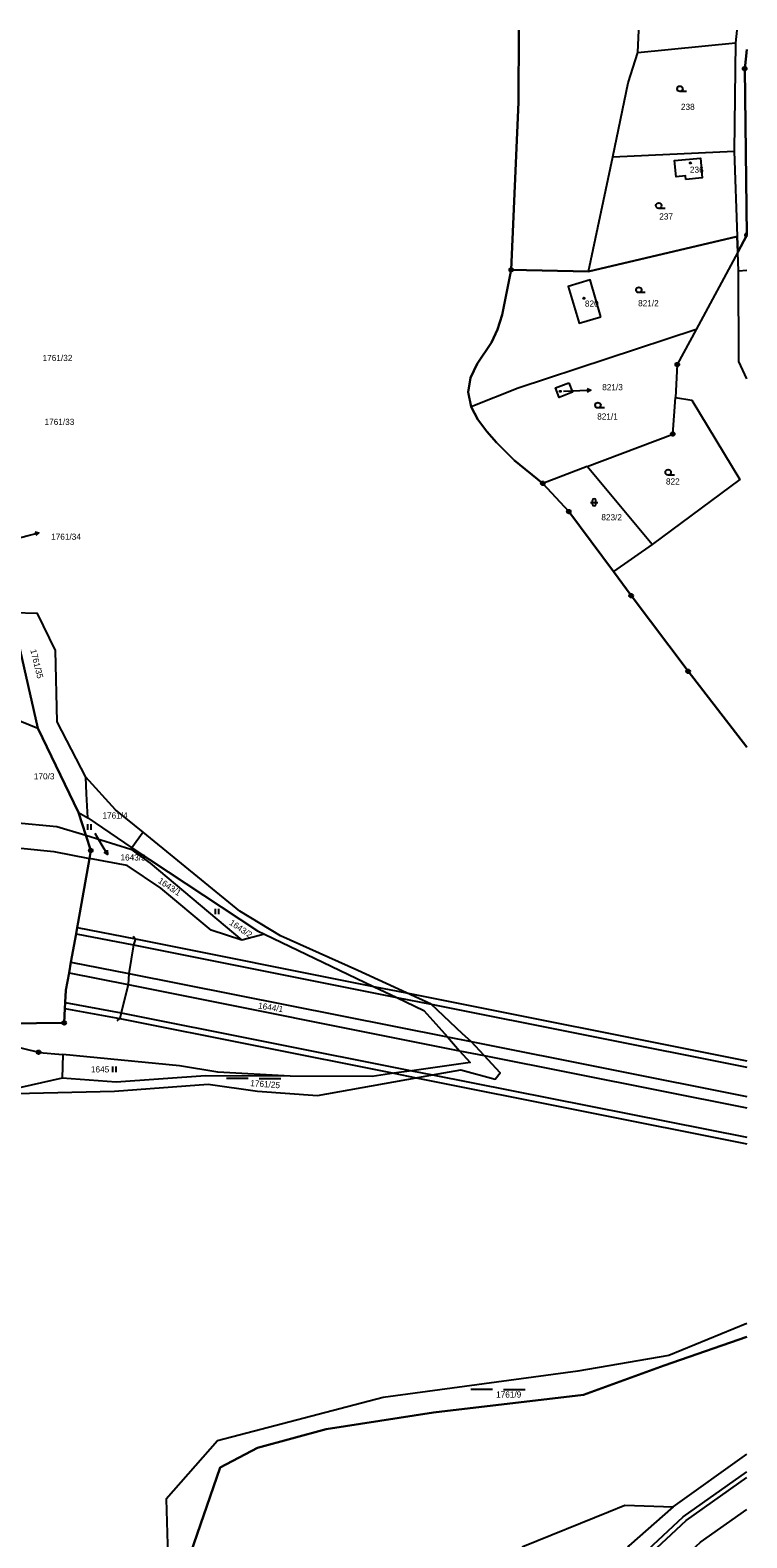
# Model space of a CAD drawing. Extents: x -737240 to -735272, y -1119606 to -1117878.
# Drawn here: x -735469.9 to -735272.2, y -1118294.6 to -1117878.3 of the extents above; entities that cross this region are included whole.
import ezdxf

# ---------------------------------------------------------------- set-up
doc = ezdxf.new("R2010")
doc.units = 0
for name, color, linetype in [('Level 1', 7, 'Continuous'), ('Level 13', 7, 'Continuous'), ('Level 16', 7, 'Continuous'), ('Level 18', 7, 'Continuous'), ('Level 19', 7, 'Continuous'), ('Level 25', 7, 'Continuous'), ('Level 4', 7, 'Continuous')]:
    doc.layers.add(name, color=color, linetype=linetype)

msp = doc.modelspace()

# ---------------------------------------------------------------- linework, layer by layer
at = {"layer": 'Level 1'}
for p, q in [((-735302.32, -1117884.48), (-735302.039, -1117878.325)), ((-735302.32, -1117884.48), (-735275.36, -1117881.8)), ((-735275.36, -1117881.8), (-735275.67, -1117911.76)), ((-735315.94, -1117944.99), (-735309.17, -1117913.32)), ((-735309.17, -1117913.32), (-735275.67, -1117911.76)), ((-735275.67, -1117911.76), (-735274.87, -1117935.26)), ((-735274.87, -1117935.26), (-735315.94, -1117944.99)), ((-735274.73, -1117939.62), (-735286.2, -1117960.98)), ((-735274.52, -1117944.82), (-735274.73, -1117939.62)), ((-735272.215, -1117944.634), (-735274.52, -1117944.82)), ((-735316.27, -1117998.81), (-735328.51, -1118003.44)), ((-735298.36, -1118020.36), (-735316.27, -1117998.81)), ((-735298.36, -1118020.36), (-735309.03, -1118027.82)), ((-735474.21, -1118042.61), (-735467.78, -1118071.06)), ((-735480.05, -1118066.06), (-735467.78, -1118071.06)), ((-735456.55, -1118094.29), (-735454.06, -1118095.76)), ((-735454.54, -1118100.61), (-735456.55, -1118094.29)), ((-735454.06, -1118095.76), (-735441.86, -1118104.02)), ((-735454.54, -1118100.61), (-735442.15, -1118104.41)), ((-735438.72, -1118099.76), (-735441.86, -1118104.02)), ((-735442.15, -1118104.41), (-735441.86, -1118104.02)), ((-735458.67, -1118135.62), (-735457.26, -1118127.77)), ((-735457.26, -1118127.77), (-735456.96, -1118126.05)), ((-735405.25, -1118127.94), (-735411.57, -1118129.59)), ((-735405.25, -1118127.94), (-735375.21, -1118142.31)), ((-735459.2, -1118138.57), (-735458.67, -1118135.62)), ((-735375.21, -1118142.31), (-735368.78, -1118145.38)), ((-735359.33, -1118147.26), (-735366.15, -1118144.12)), ((-735460.32, -1118148.43), (-735460.23, -1118146.77)), ((-735354.84, -1118156.25), (-735351.45, -1118160.06)), ((-735344.65, -1118161.42), (-735348.27, -1118157.56)), ((-735460.92, -1118161.14), (-735461.14, -1118167.68)), ((-735364.63, -1118165.59), (-735369.57, -1118166.3)), ((-735363.41, -1118167.53), (-735358.93, -1118166.72))]:
    msp.add_line(p, q, dxfattribs=at)
for points in [[(-735335.141, -1117878.325), (-735335.25, -1117898.16), (-735337.21, -1117944.47), (-735339.7, -1117956.88), (-735340.99, -1117960.95), (-735342.67, -1117964.53), (-735346.65, -1117970.41), (-735348.44, -1117974.31), (-735349.08, -1117978.3), (-735348.29, -1117982.28), (-735346.42, -1117985.78), (-735343.95, -1117989.17), (-735341.25, -1117992.15), (-735336.29, -1117997.14), (-735328.51, -1118003.44), (-735321.34, -1118011.23), (-735309.03, -1118027.82), (-735304.12, -1118034.44), (-735288.4, -1118055.33), (-735272.215, -1118076.285)], [(-735315.94, -1117944.99), (-735337.21, -1117944.47), (-735335.25, -1117898.16), (-735335.141, -1117878.325)], [(-735274.971, -1117878.325), (-735275.36, -1117881.8)], [(-735309.17, -1117913.32), (-735304.94, -1117892.88), (-735302.32, -1117884.48)], [(-735272.215, -1117883.646), (-735272.81, -1117888.96), (-735272.23, -1117934.9), (-735274.73, -1117939.62), (-735274.87, -1117935.26)], [(-735274.73, -1117939.62), (-735272.23, -1117934.9), (-735272.81, -1117888.96), (-735272.215, -1117883.646)], [(-735289.03, -1117919.53), (-735289.16, -1117918.58), (-735291.7, -1117918.79), (-735292.2, -1117914.33), (-735285.02, -1117913.65), (-735284.56, -1117919.07), (-735289.03, -1117919.53)], [(-735348.29, -1117982.28), (-735349.08, -1117978.3), (-735348.44, -1117974.31), (-735346.65, -1117970.41), (-735342.67, -1117964.53), (-735340.99, -1117960.95), (-735339.7, -1117956.88), (-735337.21, -1117944.47), (-735315.94, -1117944.99), (-735274.87, -1117935.26), (-735274.73, -1117939.62)], [(-735272.215, -1117974.589), (-735274.38, -1117969.78), (-735274.52, -1117944.82)], [(-735312.45, -1117957.43), (-735315.45, -1117947.25), (-735321.49, -1117949.1), (-735318.45, -1117959.2), (-735312.45, -1117957.43)], [(-735286.2, -1117960.98), (-735335.32, -1117977.17), (-735348.29, -1117982.28)], [(-735286.2, -1117960.98), (-735291.4, -1117970.66), (-735291.93, -1117979.78)], [(-735321.31, -1117975.66), (-735320.3, -1117978.23), (-735323.95, -1117979.72), (-735324.98, -1117977.11), (-735321.31, -1117975.66)], [(-735316.27, -1117998.81), (-735292.65, -1117989.82), (-735291.93, -1117979.78)], [(-735291.93, -1117979.78), (-735287.35, -1117980.48), (-735274.19, -1118002.37), (-735298.36, -1118020.36)], [(-735328.51, -1118003.44), (-735336.29, -1117997.14), (-735341.25, -1117992.15), (-735343.95, -1117989.17), (-735346.42, -1117985.78), (-735348.29, -1117982.28)], [(-735309.03, -1118027.82), (-735321.34, -1118011.23), (-735328.51, -1118003.44)], [(-735272.215, -1118076.285), (-735288.4, -1118055.33), (-735304.12, -1118034.44), (-735309.03, -1118027.82)], [(-735454.6, -1118084.55), (-735462.52, -1118069.26), (-735462.98, -1118049.57), (-735467.95, -1118039.37), (-735474.64, -1118039.23)], [(-735456.55, -1118094.29), (-735467.78, -1118071.06), (-735474.21, -1118042.61), (-735474.64, -1118039.23)], [(-735467.78, -1118071.06), (-735456.55, -1118094.29), (-735454.54, -1118100.61)], [(-735438.72, -1118099.76), (-735446.4, -1118093.58), (-735454.6, -1118084.55)], [(-735454.06, -1118095.76), (-735454.38, -1118089.18), (-735454.6, -1118084.55)], [(-735579.33, -1118095.15), (-735568.89, -1118093.26), (-735558.52, -1118091.47), (-735530.46, -1118097.79), (-735509.01, -1118100.58), (-735486.22, -1118102.79), (-735463.38, -1118105.12), (-735453.59, -1118106.97)], [(-735474.25, -1118097.08), (-735462.56, -1118098.15), (-735454.54, -1118100.61)], [(-735453.59, -1118106.97), (-735453.21, -1118104.78), (-735454.54, -1118100.61)], [(-735454.54, -1118100.61), (-735453.21, -1118104.78), (-735453.59, -1118106.97)], [(-735366.15, -1118144.12), (-735379.56, -1118137.95), (-735400.88, -1118128.34), (-735412.11, -1118121.55), (-735438.72, -1118099.76)], [(-735442.15, -1118104.41), (-735436.86, -1118108.31), (-735411.57, -1118129.59)], [(-735441.86, -1118104.02), (-735407.2, -1118127), (-735405.25, -1118127.94)], [(-735453.59, -1118106.97), (-735456.7, -1118124.63), (-735456.96, -1118126.05), (-735457.26, -1118127.77), (-735458.67, -1118135.62), (-735459.2, -1118138.57), (-735460.06, -1118143.37), (-735460.23, -1118146.77), (-735460.32, -1118148.43), (-735460.52, -1118152.38), (-735498.86, -1118152.84)], [(-735456.96, -1118126.05), (-735456.7, -1118124.63), (-735453.59, -1118106.97)], [(-735411.57, -1118129.59), (-735420.01, -1118126.78), (-735433.86, -1118115.2), (-735443.13, -1118108.94), (-735453.59, -1118106.97)], [(-735460.23, -1118146.77), (-735460.06, -1118143.37), (-735459.2, -1118138.57)], [(-735368.78, -1118145.38), (-735361.32, -1118148.95), (-735357.22, -1118153.56), (-735354.84, -1118156.25)], [(-735498.86, -1118152.84), (-735460.52, -1118152.38), (-735460.32, -1118148.43)], [(-735348.27, -1118157.56), (-735350.65, -1118155.4), (-735359.33, -1118147.26)], [(-735498.86, -1118152.84), (-735467.59, -1118160.48), (-735467.44, -1118160.52), (-735460.92, -1118161.14)], [(-735398.18, -1118167.09), (-735418.17, -1118166.01), (-735428.76, -1118164.21), (-735460.92, -1118161.14)], [(-735351.45, -1118160.06), (-735348.58, -1118163.3), (-735364.63, -1118165.59)], [(-735358.93, -1118166.72), (-735351.14, -1118165.32), (-735341.68, -1118167.89), (-735340.24, -1118166.18), (-735344.65, -1118161.42)], [(-735398.18, -1118167.09), (-735421.53, -1118167.01), (-735446.22, -1118168.76), (-735461.14, -1118167.68)], [(-735369.57, -1118166.3), (-735375.58, -1118167.16), (-735398.18, -1118167.09)], [(-735498.68, -1118177.89), (-735474.03, -1118171.91), (-735446.66, -1118171.24), (-735420.82, -1118169.27), (-735407.2, -1118171.25), (-735390.63, -1118172.43), (-735363.41, -1118167.53)], [(-735461.14, -1118167.68), (-735493.41, -1118174.96), (-735498.68, -1118177.89)], [(-735272.215, -1118235.352), (-735293.73, -1118244.25), (-735318.8, -1118248.55), (-735372.51, -1118255.8), (-735418.29, -1118267.78), (-735432.38, -1118283.91), (-735431.72, -1118305.77), (-735410.26, -1118327.63), (-735378.55, -1118363.01), (-735338.79, -1118385.27), (-735323.79, -1118431.69), (-735325.65, -1118460.46), (-735322.24, -1118495.31), (-735329.74, -1118504.27)], [(-735320.79, -1118502.01), (-735316, -1118477.93), (-735319.58, -1118455.39), (-735324.75, -1118410.55), (-735334.33, -1118387.43), (-735339.07, -1118376.71), (-735356.26, -1118364.47), (-735377.56, -1118357.98), (-735407.91, -1118326.17), (-735426.65, -1118301.52), (-735417.49, -1118275.12), (-735407.21, -1118269.69), (-735388.3, -1118264.58), (-735358.65, -1118259.95), (-735317.23, -1118255.09), (-735295.06, -1118246.97), (-735272.215, -1118239.048)], [(-735272.215, -1118239.048), (-735295.06, -1118246.97), (-735317.23, -1118255.09), (-735358.65, -1118259.95), (-735388.3, -1118264.58), (-735407.21, -1118269.69), (-735417.49, -1118275.12), (-735426.65, -1118301.52), (-735407.91, -1118326.17), (-735377.56, -1118357.98), (-735356.26, -1118364.47), (-735339.07, -1118376.71), (-735334.33, -1118387.43), (-735324.75, -1118410.55), (-735319.58, -1118455.39), (-735316, -1118477.93), (-735320.79, -1118502.01)], [(-735292.51, -1118286), (-735272.215, -1118271.427)], [(-735272.215, -1118440.225), (-735276.71, -1118433.48), (-735291.7, -1118402.57), (-735296.36, -1118385.95), (-735298.9, -1118380.74), (-735301.95, -1118374.49), (-735316.69, -1118355.57), (-735328.83, -1118332.98), (-735333.78, -1118311.44), (-735334.01, -1118296.9), (-735310.42, -1118287.41), (-735305.85, -1118285.57), (-735292.51, -1118286)], [(-735292.51, -1118286), (-735292.57, -1118286.04), (-735304.75, -1118296.77), (-735310.25, -1118306.23), (-735311.37, -1118310), (-735314.09, -1118319.12), (-735315.58, -1118339.66), (-735309.98, -1118358.63), (-735298.87, -1118373.57), (-735282.99, -1118391.11), (-735272.215, -1118403.546)]]:
    msp.add_lwpolyline(points, dxfattribs=at)
at = {"layer": 'Level 13'}
for points in [[(-735335.141, -1117878.325), (-735335.25, -1117898.16), (-735337.21, -1117944.47), (-735339.7, -1117956.88), (-735340.99, -1117960.95), (-735342.67, -1117964.53), (-735346.65, -1117970.41), (-735348.44, -1117974.31), (-735349.08, -1117978.3), (-735348.29, -1117982.28), (-735346.42, -1117985.78), (-735343.95, -1117989.17), (-735341.25, -1117992.15), (-735336.29, -1117997.14), (-735328.51, -1118003.44), (-735321.34, -1118011.23), (-735309.03, -1118027.82), (-735304.12, -1118034.44), (-735288.4, -1118055.33), (-735272.215, -1118076.285)], [(-735272.215, -1117883.646), (-735272.81, -1117888.96), (-735272.23, -1117934.9), (-735274.73, -1117939.62), (-735274.87, -1117935.26), (-735315.94, -1117944.99), (-735337.21, -1117944.47), (-735335.25, -1117898.16), (-735335.141, -1117878.325)], [(-735272.215, -1117883.646), (-735272.81, -1117888.96), (-735272.23, -1117934.9), (-735274.73, -1117939.62), (-735274.87, -1117935.26), (-735315.94, -1117944.99), (-735337.21, -1117944.47), (-735339.7, -1117956.88), (-735340.99, -1117960.95), (-735342.67, -1117964.53), (-735346.65, -1117970.41), (-735348.44, -1117974.31), (-735349.08, -1117978.3), (-735348.29, -1117982.28), (-735346.42, -1117985.78), (-735343.95, -1117989.17), (-735341.25, -1117992.15), (-735336.29, -1117997.14), (-735328.51, -1118003.44), (-735321.34, -1118011.23), (-735309.03, -1118027.82), (-735304.12, -1118034.44), (-735288.4, -1118055.33), (-735272.215, -1118076.285)], [(-735498.86, -1118152.84), (-735460.52, -1118152.38), (-735460.32, -1118148.43), (-735460.23, -1118146.77), (-735460.06, -1118143.37), (-735459.2, -1118138.57), (-735458.67, -1118135.62), (-735457.26, -1118127.77), (-735456.96, -1118126.05), (-735456.7, -1118124.63), (-735453.59, -1118106.97), (-735453.21, -1118104.78), (-735454.54, -1118100.61), (-735456.55, -1118094.29), (-735467.78, -1118071.06), (-735474.21, -1118042.61)], [(-735474.21, -1118042.61), (-735467.78, -1118071.06), (-735456.55, -1118094.29), (-735454.54, -1118100.61), (-735453.21, -1118104.78), (-735453.59, -1118106.97), (-735456.7, -1118124.63), (-735456.96, -1118126.05), (-735457.26, -1118127.77), (-735458.67, -1118135.62), (-735459.2, -1118138.57), (-735460.06, -1118143.37), (-735460.23, -1118146.77), (-735460.32, -1118148.43), (-735460.52, -1118152.38), (-735498.86, -1118152.84)], [(-735272.215, -1118239.048), (-735295.06, -1118246.97), (-735317.23, -1118255.09), (-735358.65, -1118259.95), (-735388.3, -1118264.58), (-735407.21, -1118269.69), (-735417.49, -1118275.12), (-735426.65, -1118301.52)], [(-735272.215, -1118239.048), (-735295.06, -1118246.97), (-735317.23, -1118255.09), (-735358.65, -1118259.95), (-735388.3, -1118264.58), (-735407.21, -1118269.69), (-735417.49, -1118275.12), (-735426.65, -1118301.52), (-735407.91, -1118326.17), (-735377.56, -1118357.98), (-735356.26, -1118364.47), (-735339.07, -1118376.71), (-735334.33, -1118387.43), (-735324.75, -1118410.55), (-735319.58, -1118455.39), (-735316, -1118477.93), (-735320.79, -1118502.01), (-735332.63, -1118511.79)]]:
    msp.add_lwpolyline(points, dxfattribs=at)
at = {"layer": 'Level 16'}
for points in [[(-735322.76, -1117977.97), (-735318.24, -1117977.83), (-735315.241, -1117977.738)], [(-735316.256, -1117977.269), (-735315.241, -1117977.738), (-735316.226, -1117978.269)], [(-735475.37, -1118019.11), (-735470.44, -1118017.84), (-735467.535, -1118017.091)], [(-735468.628, -1118016.857), (-735467.535, -1118017.091), (-735468.379, -1118017.825)], [(-735452.12, -1118100.04), (-735450.13, -1118103.3), (-735448.568, -1118105.861)], [(-735448.662, -1118104.747), (-735448.568, -1118105.861), (-735449.515, -1118105.268)]]:
    msp.add_lwpolyline(points, dxfattribs=at)
at = {"layer": 'Level 25'}
for p, q in [((-735288.888, -1117895.27), (-735290.67, -1117895.27)), ((-735294.728, -1117927.53), (-735296.51, -1117927.53)), ((-735272.215, -1117935.408), (-735272.215, -1117934.392)), ((-735272.215, -1117934.934), (-735272.215, -1117934.866)), ((-735300.238, -1117950.79), (-735302.02, -1117950.79)), ((-735311.518, -1117982.63), (-735313.3, -1117982.63)), ((-735292.138, -1118001.16), (-735293.92, -1118001.16)), ((-735315.33, -1118008.69), (-735313.33, -1118008.69)), ((-735314.83, -1118009.19), (-735314.83, -1118008.19)), ((-735313.83, -1118009.19), (-735313.83, -1118008.19)), ((-735454.127, -1118097.555), (-735454.127, -1118099.055)), ((-735453.105, -1118099.055), (-735453.105, -1118097.555)), ((-735418.867, -1118120.875), (-735418.867, -1118122.375)), ((-735417.845, -1118122.375), (-735417.845, -1118120.875)), ((-735441.489, -1118128.413), (-735440.86, -1118129.19)), ((-735445.917, -1118151.842), (-735445.15, -1118151.2)), ((-735447.187, -1118164.455), (-735447.187, -1118165.955)), ((-735446.165, -1118165.955), (-735446.165, -1118164.455)), ((-735409.77, -1118167.7), (-735415.77, -1118167.7)), ((-735406.77, -1118167.7), (-735400.77, -1118167.7)), ((-735342.35, -1118253.64), (-735348.35, -1118253.64)), ((-735339.35, -1118253.64), (-735333.35, -1118253.64))]:
    msp.add_line(p, q, dxfattribs=at)
for centre, start, end in [((-735314.33, -1118008.19), 0, 180), ((-735314.33, -1118009.19), 180, 0)]:
    msp.add_arc(centre, 0.5, start, end, dxfattribs=at)
for centre, major_axis, ratio in [((-735272.81, -1117888.96), (0.516, 0), 0.9848078), ((-735272.81, -1117888.96), (0.0375, 0), 0.9848078), ((-735290.67, -1117894.514), (0.764, 0), 0.9894236), ((-735287.79, -1117914.97), (0.18, 0), 0.9848078), ((-735296.51, -1117926.774), (0.764, 0), 0.9894236), ((-735337.21, -1117944.47), (0.516, 0), 0.9848078), ((-735337.21, -1117944.47), (0.0375, 0), 0.9848078), ((-735302.02, -1117950.034), (0.764, 0), 0.9894236), ((-735317.17, -1117952.35), (0.18, 0), 0.9848078), ((-735291.4, -1117970.66), (0.516, 0), 0.9848078), ((-735291.4, -1117970.66), (0.0375, 0), 0.9848078), ((-735323.69, -1117978.04), (0.18, 0), 0.9848078), ((-735313.3, -1117981.874), (0.764, 0), 0.9894236), ((-735292.65, -1117989.82), (0.516, 0), 0.9848078), ((-735292.65, -1117989.82), (0.0375, 0), 0.9848078), ((-735293.92, -1118000.404), (0.764, 0), 0.9894236), ((-735328.51, -1118003.44), (0.516, 0), 0.9848078), ((-735328.51, -1118003.44), (0.0375, 0), 0.9848078), ((-735321.34, -1118011.23), (0.516, 0), 0.9848078), ((-735321.34, -1118011.23), (0.0375, 0), 0.9848078), ((-735304.12, -1118034.44), (0.516, 0), 0.9848078), ((-735304.12, -1118034.44), (0.0375, 0), 0.9848078), ((-735288.4, -1118055.33), (0.516, 0), 0.9848078), ((-735288.4, -1118055.33), (0.0375, 0), 0.9848078), ((-735453.21, -1118104.78), (0.516, 0), 0.9848078), ((-735453.21, -1118104.78), (0.0375, 0), 0.9848078), ((-735460.52, -1118152.38), (0.516, 0), 0.9848078), ((-735460.52, -1118152.38), (0.0375, 0), 0.9848078), ((-735467.59, -1118160.48), (0.516, 0), 0.9848078), ((-735467.59, -1118160.48), (0.0375, 0), 0.9848078)]:
    msp.add_ellipse(centre, major_axis=major_axis, ratio=ratio, dxfattribs=at)
for major_axis, start_param, end_param in [((0.516, 0), 1.5419301, 4.7412552), ((0.0375, 0), 1.1626964, 5.1204889)]:
    msp.add_ellipse((-735272.23, -1117934.9), major_axis=major_axis, ratio=0.9848078, start_param=start_param, end_param=end_param, dxfattribs=at)
at = {"layer": 'Level 4'}
for p, q in [((-735457.26, -1118127.77), (-735441.46, -1118130.88)), ((-735456.96, -1118126.05), (-735440.86, -1118129.19)), ((-735440.86, -1118129.19), (-735441.46, -1118130.88)), ((-735440.86, -1118129.19), (-735375.21, -1118142.31)), ((-735441.46, -1118130.88), (-735442.7, -1118138.75)), ((-735441.46, -1118130.88), (-735368.78, -1118145.38)), ((-735458.67, -1118135.62), (-735442.7, -1118138.75)), ((-735459.2, -1118138.57), (-735442.93, -1118141.81)), ((-735442.93, -1118141.81), (-735444.87, -1118149.62)), ((-735442.7, -1118138.75), (-735442.93, -1118141.81)), ((-735442.93, -1118141.81), (-735351.45, -1118160.06)), ((-735442.7, -1118138.75), (-735354.84, -1118156.25)), ((-735375.21, -1118142.31), (-735366.15, -1118144.12)), ((-735368.78, -1118145.38), (-735359.33, -1118147.26)), ((-735366.15, -1118144.12), (-735272.215, -1118162.889)), ((-735460.32, -1118148.43), (-735445.15, -1118151.2)), ((-735460.23, -1118146.77), (-735444.87, -1118149.62)), ((-735444.87, -1118149.62), (-735445.15, -1118151.2)), ((-735444.87, -1118149.62), (-735364.63, -1118165.59)), ((-735359.33, -1118147.26), (-735272.215, -1118164.645)), ((-735445.15, -1118151.2), (-735369.57, -1118166.3)), ((-735354.84, -1118156.25), (-735348.27, -1118157.56)), ((-735348.27, -1118157.56), (-735272.215, -1118172.703)), ((-735351.45, -1118160.06), (-735344.65, -1118161.42)), ((-735344.65, -1118161.42), (-735272.215, -1118175.869)), ((-735369.57, -1118166.3), (-735363.41, -1118167.53)), ((-735364.63, -1118165.59), (-735358.93, -1118166.72)), ((-735358.93, -1118166.72), (-735272.215, -1118183.985)), ((-735363.41, -1118167.53), (-735272.215, -1118185.749))]:
    msp.add_line(p, q, dxfattribs=at)
for points in [[(-735272.215, -1118400.074), (-735281.2, -1118389.67), (-735296.58, -1118371.7), (-735306.82, -1118356.55), (-735312.05, -1118339.16), (-735310.99, -1118319.62), (-735306.44, -1118307.82), (-735300.82, -1118299.05), (-735289.82, -1118288.75), (-735272.215, -1118276.309)], [(-735272.215, -1118398.051), (-735280.24, -1118388.77), (-735295.66, -1118370.74), (-735305.63, -1118355.81), (-735310.69, -1118338.79), (-735309.66, -1118319.96), (-735305.25, -1118308.43), (-735299.78, -1118299.91), (-735288.96, -1118289.73), (-735272.215, -1118277.928)], [(-735272.215, -1118387.708), (-735275.4, -1118384.01), (-735290.61, -1118366.22), (-735299.66, -1118352.37), (-735303.58, -1118337.54), (-735302.49, -1118321.2), (-735298.83, -1118311.15), (-735293.41, -1118303.47), (-735284.95, -1118295.71), (-735272.215, -1118286.687)]]:
    msp.add_lwpolyline(points, dxfattribs=at)

# ---------------------------------------------------------------- texts
at = {"layer": 'Level 16'}
for s, p in [('1761/32', (-735466.505, -1117969.67)), ('821/3', (-735312.115, -1117977.74)), ('1761/33', (-735465.965, -1117987.32)), ('1761/34', (-735464.145, -1118019.02)), ('1643/3', (-735445.02, -1118107.56))]:
    msp.add_text(s, height=1.7, dxfattribs=at).set_placement(p)
at = {"layer": 'Level 18'}
for s, height, p in [('238', 1.7, (-735290.39, -1117900.34)), ('237', 1.7, (-735296.38, -1117930.6)), ('821/2', 1.7, (-735302.205, -1117954.55)), ('821/1', 1.7, (-735313.495, -1117985.82)), ('822', 1.7, (-735294.525, -1118003.76)), ('823/2', 1.7, (-735312.35, -1118013.65)), ('170/3', 1.7, (-735468.91, -1118085.17)), ('1761/4', 1.7, (-735449.99, -1118095.98)), ('1643/3', 0.1, (-735451.97, -1118100.04)), ('1645', 1.7, (-735453.17, -1118166.07)), ('1761/9', 1.7, (-735341.39, -1118255.84))]:
    msp.add_text(s, height=height, dxfattribs=at).set_placement(p)
for s, rotation, p in [('1761/35', 283.97853, (-735469.901, -1118049.487)), ('1643/1', 326.32704, (-735434.828, -1118113.574)), ('1643/2', 325.96299, (-735415.147, -1118125.127)), ('1644/1', 351.24354, (-735407.13, -1118148.408)), ('1761/25', 355.67406, (-735409.253, -1118169.834))]:
    msp.add_text(s, height=1.7, rotation=rotation, dxfattribs=at).set_placement(p)
at = {"layer": 'Level 19'}
for s, height, p in [('236', 1.7, (-735287.92, -1117917.7)), ('820', 1.7, (-735316.88, -1117954.67)), ('821/3', 0.1, (-735322.61, -1117977.97))]:
    msp.add_text(s, height=height, dxfattribs=at).set_placement(p)

doc.saveas('drawing.dxf')
